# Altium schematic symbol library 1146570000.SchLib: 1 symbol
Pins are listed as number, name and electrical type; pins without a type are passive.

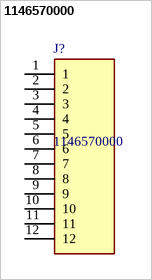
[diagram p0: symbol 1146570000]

## 1146570000
designator J?
PCB plug-in connector, male header, open side, THT solder connection, 5.08 mm, Number of poles: 12, 180, Solder pin length: 3.2 mm, tinned, orange, Box; Manufacturer_Name: Weidmuller; Geometry.Height: 12mm
footprint 1146570000
pins: 1, 2, 3, 4, 5, 6, 7, 8, 9, 10, 11, 12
